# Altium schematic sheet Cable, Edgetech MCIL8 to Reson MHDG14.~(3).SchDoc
size B; Organization: Monterey Bay Aquarium Research Institute; Address1: 7700 Sandholdt Rd; Address2: Moss Landing, CA 95039-9644; CompanyName: MBARI
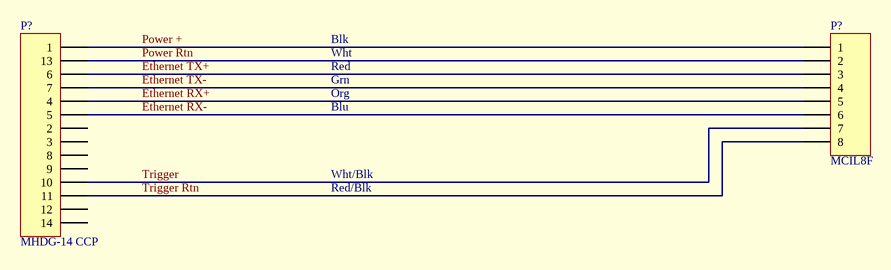
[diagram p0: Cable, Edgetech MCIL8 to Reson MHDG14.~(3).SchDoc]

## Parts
(Parts that share a designator on the sheet are numbered #1, #2 ... from top to bottom, then left to right.)
P?#1  MHDG-14 CCP  [HDR1X14]
P?#2  MCIL8F  [HDR1X8]

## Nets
Ethernet RX+: P?#1.4 P?#2.5
Ethernet RX-: P?#1.5 P?#2.6
Ethernet TX+: P?#1.6 P?#2.3
Ethernet TX-: P?#1.7 P?#2.4
Power +: P?#1.1 P?#2.1
Power Rtn: P?#1.13 P?#2.2
Trigger: P?#1.10 P?#2.7
Trigger Rtn: P?#1.11 P?#2.8

Not connected (* = marked no-connect by the designer): P?#1 2 3 8 9 12 14

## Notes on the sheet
- Blk
- Wht
- Red
- Grn
- Org
- Blu
- Wht/Blk
- Red/Blk

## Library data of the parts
P?#1 = Header 14: Header, 14-Pin
P?#2 = Header 8: Header, 8-Pin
